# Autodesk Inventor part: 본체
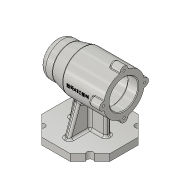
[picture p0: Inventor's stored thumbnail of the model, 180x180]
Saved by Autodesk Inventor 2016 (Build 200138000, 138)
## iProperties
Created: 2021-01
Part Number: 본체
Material: 알루미늄 6061
Document SubType Name: Modeling
Designer: Administrator
Density: 2.7 g/cm^3
Appearance: 알루미늄 - 평지
Mass: 629.963 g
Surface Area: 613.774 cm^2
Volume: 233.32 cm^3
Author: Administrator
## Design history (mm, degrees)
sketch "스케치1"
  geometry: L1 (-50, 0)-(50, 0); L2 (-50, 0)-(-50, 25); L3 (-50, 25)-(-30, 25); L4 (-30, 25)-(-10, 30); L5 (-10, 30)-(50, 30); L6 (50, 30)-(50, 21); L7 (50, 21)-(35, 21); L8 (35, 21)-(35, 24); L9 (35, 24)-(-7, 24); L10 (-7, 24)-(-7, 21); L11 (-7, 21)-(-19, 21); L12 (-19, 21)-(-19, 17.5); L13 (-19, 17.5)-(-37, 17.5); L14 (-37, 17.5)-(-37, 16); L15 (-37, 16)-(-41, 16); L16 (-41, 16)-(-41, 10.5); L17 (-41, 10.5)-(-44, 10.5); L18 (-44, 10.5)-(-44, 0); 1 further point
  constraints: 36 end point, 14 perpendicular, 1 horizontal, 1 midpoint, 1 parallel, 1 point on line, 1 vertical, 1 vertical alignment
  dimensions: "d0" = 100 distance of L1.start L1.end; "d1" = 50 distance of point (0, 0) L1.start; "d2" = 50 diameter of L3 L1; "d3" = 60 diameter of L5 L1; "d4" = 42 diameter of L7 L1; "d5" = 48 diameter of L9 L1; "d6" = 42 diameter of L11 L1; "d7" = 35 diameter of L13 L1; "d8" = 32 diameter of L15 L1; "d9" = 21 diameter of L17 L1; "d10" = 15 distance between parallel lines of L8 L6; "d11" = 42 distance between parallel lines of L10 L8; "d12" = 12 distance between parallel lines of L12 L10; "d13" = 18 distance between parallel lines of L14 L12; "d14" = 4 distance between parallel lines of L16 L14; "d15" = 3 distance between parallel lines of L18 L16; "d16" = 20 distance of L3.end L2.end; "d17" = 40 horizontal distance of L4.end L2.end
revolve "회전1" sketch "스케치1" stored, may be unused: angle "d18" = 90 deg
node "작업 평면1"
sketch "스케치2" dims "d20" = 100
  geometry: L1 (-20.711, -50)-(-50, -20.711); L2 (-50, -20.711)-(-50, 20.711); L3 (-50, 20.711)-(-20.711, 50); L4 (-20.711, 50)-(20.711, 50); L5 (20.711, 50)-(50, 20.711); L6 (50, 20.711)-(50, -20.711); L7 (50, -20.711)-(20.711, -50); L8 (20.711, -50)-(-20.711, -50); 4 further points
  constraints: 16 end point, 2 coincident, 2 vertical alignment, 1 midpoint, 19 other
extrude "돌출1" join sketch "스케치2" distance "d21" = 10; taper "d22" = 0 deg
sketch "스케치5"
  geometry: L1 (0, 4)-(27, 4); L2 (27, 4)-(27, -4); L3 (27, -4)-(0, -4); L4 (0, -4)-(0, 4); L5 (50, 20.711)-(50, -20.711) reference; 1 further point
  constraints: 8 end point, 2 parallel, 1 horizontal, 1 perpendicular, 1 vertical alignment
  dimensions: "d33" = 8 distance of L1.end L2.end; "d34" = 23 distance between parallel lines of L5 L2; "d35" = 4 distance of point (0, 0) L1.start
extrude "돌출3" join sketch "스케치5" stored distance "d36" = 10; taper "d37" = 0 deg
sketch "스케치6"
  geometry: L1 (0, -65)-(0, -29.732) reference; L2 (-10, -30)-(50, -30) reference; L3 (-30, -25)-(-10, -30) reference; L4 (-20.711, -65)-(-50, -65) reference; L5 (20.711, -65)-(-20.711, -65) reference; L6 (-19.724, -27.569)-(-27, -65); 1 further point
  constraints: 2 end point, 2 point on line
  dimensions: "d38" = 23 distance of L6.end L4.end; "d39" = 101 deg angle of L4 L6
feature "리브1" sketch "스케치6" dims "d40" = 1, "d41" = 8, "d42" = 0, "d43" = 0, "d44" = 1, "d45" = 1
sketch "스케치7"
  geometry: L1 (-65, -20.711)-(-65, 20.711) reference; L2 (-65, 20.711)-(-65, 50) reference; L3 (-65, 4)-(-27.291, 4) reference; L4 (-22.707, 19.606)-(-65, 35); A1 r 30 centre (0, 0) between (-29.732, -4) and (-29.732, 4) reference; 1 further point
  constraints: 2 end point, 1 point on circle, 1 point on line
  dimensions: "d46" = 15 distance of L4.end L2.end; "d47" = 110 deg angle of L2 L4
feature "리브2" sketch "스케치7" dims "d48" = 1, "d49" = 8, "d50" = 0, "d51" = 0, "d52" = 1, "d53" = 1
sketch "스케치8"
  geometry: A1 r 30 centre (0, 0) between (4, -29.732) and (-4, -29.732) reference; A2 r 30 centre (0, 0) between (4, -29.732) and (-4, -29.732) reference; A3 r 6 centre (0, 30) between (5.97, 29.4) and (-5.97, 29.4); A4 r 6 centre (0, 30) between (-5.97, 29.4) and (5.97, 29.4); 1 further point
  constraints: 8 point on circle, 2 centre point, 1 vertical alignment
  dimensions: "d54" = 6 radius of A3
extrude "돌출4" join sketch "스케치8" distance "d55" = 16; taper "d56" = 0 deg
hole "구멍1" diameter "d62" = 3.242; stored, may be unused: countersink angle "d66" = 90 deg, drill point angle "d68" = 120 deg; dims "d60" = 10, "d61" = 10, "d63" = 8, "d64" = 4, "d65" = 2, "d67" = 10
sketch "스케치10"
  geometry: L1 (-50, 20.711)-(-20.711, 50) reference; L2 (0, 0)-(-50, 0); L3 (-50, -20.711)-(-50, 20.711) reference; L4 (0, 0)-(-35.355, 35.355); L5 (-20.711, -50)-(-50, -20.711) reference; L6 (0, 0)-(-35.355, -35.355); C1 r 4.5 at (-35.355, 35.355); C2 r 4.5 at (-35.355, -35.355); 1 further point
  constraints: 6 end point, 5 midpoint, 2 centre point, 1 coincident
  dimensions: "d72" = 9 diameter of C1; "d73" = 45 deg angle of L2 L4; "d78" = 45 deg angle of L2 L6; "d79" = 9 diameter of C2
extrude "돌출5" cut sketch "스케치10" stored distance "d74" = 16; taper "d75" = 0 deg
chamfer "모따기1" distance "d80" = 1; stored, may be unused: second distance "d81" = 2, angle "d82" = 45 deg
fillet "모깎기1" dims "d83" = 0.3
fillet "모깎기2" dims "d84" = 3
fillet "모깎기3" dims "d85" = 10
fillet "모깎기4" dims "d86" = 3
fillet "모깎기5" dims "d87" = 1
fillet "모깎기6" dims "d88" = 3
fillet "모깎기7" dims "d89" = 3
node "작업 평면2"
sketch "스케치11"
  geometry: L1 (30, 6.771)-(30, 29.226) reference; 2 further points
  constraints: 1 horizontal alignment, 1 other
  dimensions: "d90" = 38 distance from line of L1 point (-8, 0)
feature "엠보싱1" sketch "스케치11" dims "d91" = 0.5, "d92" = 0
node "솔리드1"
mirror "대칭1"
pattern_circular "원형 패턴1" dims angle "d58" = 360 deg
pattern_circular "원형 패턴2" dims angle "d70" = 360 deg
mirror "대칭2"
other parameters: "d19" = -75
